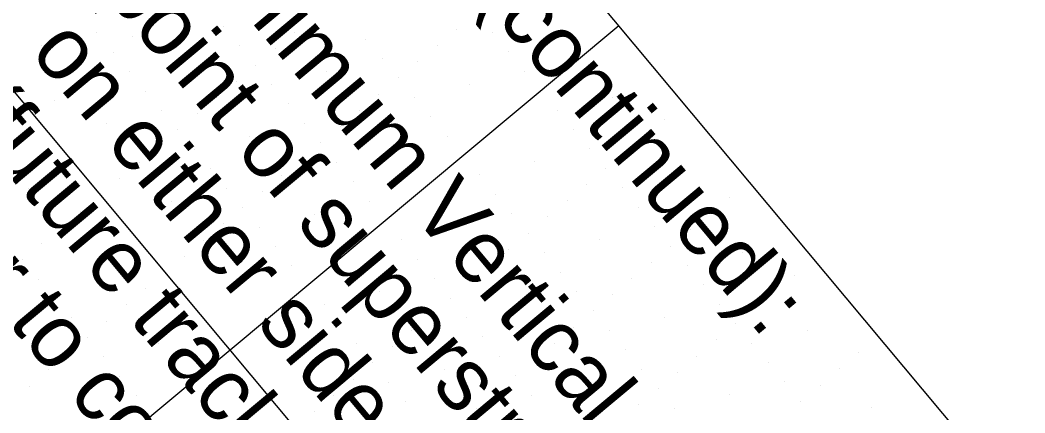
# Model space of a CAD drawing. Extents: x 2042995 to 2043795, y 305365 to 306249.
# Drawn here: x 2043491.39 to 2043531.08, y 305664.77 to 305680.3 of the extents above; entities that cross this region are included whole.
import ezdxf

# ---------------------------------------------------------------- set-up
doc = ezdxf.new("R2010")
doc.units = 0
for name, color, linetype in [('BR_AUTO DIMENSION', 7, 'Continuous'), ('BR_BORDER LINES', 7, 'Continuous'), ('BR_CONCRETE', 7, 'Continuous'), ('BR_GRID DOTS', 7, 'Continuous'), ('BR_GRID LINES', 7, 'Continuous')]:
    doc.layers.add(name, color=color, linetype=linetype)

msp = doc.modelspace()

# ---------------------------------------------------------------- linework, layer by layer
at = {"layer": 'BR_BORDER LINES'}
msp.add_line((2043183.839, 306076.621), (2043615.462, 305559.826), dxfattribs=at)
at = {"layer": 'BR_CONCRETE'}
msp.add_spline([(2043139.109, 306017.548), (2043148.199, 306007.16), (2043160.233, 305993.368), (2043172.245, 305979.557), (2043184.234, 305965.727), (2043196.201, 305951.879), (2043208.145, 305938.012), (2043220.067, 305924.126), (2043231.966, 305910.221), (2043243.843, 305896.297), (2043255.698, 305882.355), (2043267.529, 305868.394), (2043279.339, 305854.414), (2043291.126, 305840.415), (2043302.89, 305826.398), (2043314.632, 305812.361), (2043326.352, 305798.306), (2043338.049, 305784.233), (2043349.724, 305770.14), (2043361.376, 305756.029), (2043373.005, 305741.899), (2043384.613, 305727.75), (2043396.197, 305713.582), (2043407.76, 305699.396), (2043419.299, 305685.191), (2043430.817, 305670.967), (2043442.311, 305656.724), (2043453.784, 305642.463), (2043465.234, 305628.182), (2043476.661, 305613.883), (2043488.066, 305599.566), (2043499.448, 305585.229), (2043510.808, 305570.874), (2043522.146, 305556.5), (2043533.461, 305542.107), (2043544.753, 305527.695), (2043547.219, 305524.543)], degree=3, dxfattribs=at)
at = {"layer": 'BR_GRID DOTS'}
for p, q in [((2043499.415, 305680.053), (2043499.415, 305680.053)), ((2043494.422, 305679.791), (2043494.422, 305679.791)), ((2043495.831, 305679.665), (2043495.831, 305679.665)), ((2043502.232, 305679.8), (2043502.232, 305679.8)), ((2043508.634, 305679.935), (2043508.634, 305679.935)), ((2043510.043, 305679.808), (2043510.043, 305679.808)), ((2043492.246, 305679.277), (2043492.246, 305679.277)), ((2043500.056, 305679.285), (2043500.056, 305679.285)), ((2043501.465, 305679.159), (2043501.465, 305679.159)), ((2043505.049, 305679.547), (2043505.049, 305679.547)), ((2043507.867, 305679.294), (2043507.867, 305679.294)), ((2043495.063, 305679.024), (2043495.063, 305679.024)), ((2043497.88, 305678.771), (2043497.88, 305678.771)), ((2043505.69, 305678.779), (2043505.69, 305678.779)), ((2043510.684, 305679.041), (2043510.684, 305679.041)), ((2043494.296, 305678.383), (2043494.296, 305678.383)), ((2043500.697, 305678.518), (2043500.697, 305678.518)), ((2043507.099, 305678.653), (2043507.099, 305678.653)), ((2043495.704, 305678.256), (2043495.704, 305678.256)), ((2043503.514, 305678.265), (2043503.514, 305678.265)), ((2043506.332, 305678.012), (2043506.332, 305678.012)), ((2043511.325, 305678.273), (2043511.325, 305678.273)), ((2043493.528, 305677.742), (2043493.528, 305677.742)), ((2043499.93, 305677.877), (2043499.93, 305677.877)), ((2043501.338, 305677.75), (2043501.338, 305677.75)), ((2043509.149, 305677.759), (2043509.149, 305677.759)), ((2043496.345, 305677.489), (2043496.345, 305677.489)), ((2043499.162, 305677.236), (2043499.162, 305677.236)), ((2043505.564, 305677.371), (2043505.564, 305677.371)), ((2043506.973, 305677.244), (2043506.973, 305677.244)), ((2043514.783, 305677.253), (2043514.783, 305677.253)), ((2043492.761, 305677.101), (2043492.761, 305677.101)), ((2043501.979, 305676.983), (2043501.979, 305676.983)), ((2043491.993, 305676.46), (2043491.993, 305676.46)), ((2043496.986, 305676.721), (2043496.986, 305676.721)), ((2043498.395, 305676.595), (2043498.395, 305676.595)), ((2043504.796, 305676.73), (2043504.796, 305676.73)), ((2043507.614, 305676.477), (2043507.614, 305676.477)), ((2043512.607, 305676.738), (2043512.607, 305676.738)), ((2043494.81, 305676.207), (2043494.81, 305676.207)), ((2043502.62, 305676.215), (2043502.62, 305676.215)), ((2043504.029, 305676.089), (2043504.029, 305676.089)), ((2043516.832, 305676.359), (2043516.832, 305676.359)), ((2043497.627, 305675.954), (2043497.627, 305675.954)), ((2043500.444, 305675.701), (2043500.444, 305675.701)), ((2043508.255, 305675.709), (2043508.255, 305675.709)), ((2043513.248, 305675.971), (2043513.248, 305675.971)), ((2043516.065, 305675.718), (2043516.065, 305675.718)), ((2043496.86, 305675.313), (2043496.86, 305675.313)), ((2043498.268, 305675.186), (2043498.268, 305675.186)), ((2043503.261, 305675.448), (2043503.261, 305675.448)), ((2043506.079, 305675.195), (2043506.079, 305675.195)), ((2043513.889, 305675.203), (2043513.889, 305675.203)), ((2043502.494, 305674.807), (2043502.494, 305674.807)), ((2043515.297, 305675.077), (2043515.297, 305675.077)), ((2043496.092, 305674.671), (2043496.092, 305674.671)), ((2043498.909, 305674.419), (2043498.909, 305674.419)), ((2043503.902, 305674.68), (2043503.902, 305674.68)), ((2043511.713, 305674.689), (2043511.713, 305674.689)), ((2043514.53, 305674.436), (2043514.53, 305674.436)), ((2043495.325, 305674.03), (2043495.325, 305674.03)), ((2043501.726, 305674.166), (2043501.726, 305674.166)), ((2043509.537, 305674.174), (2043509.537, 305674.174)), ((2043517.347, 305674.183), (2043517.347, 305674.183)), ((2043491.74, 305673.642), (2043491.74, 305673.642)), ((2043499.55, 305673.651), (2043499.55, 305673.651)), ((2043504.543, 305673.913), (2043504.543, 305673.913)), ((2043513.762, 305673.795), (2043513.762, 305673.795)), ((2043515.171, 305673.668), (2043515.171, 305673.668)), ((2043494.557, 305673.389), (2043494.557, 305673.389)), ((2043500.959, 305673.525), (2043500.959, 305673.525)), ((2043510.178, 305673.407), (2043510.178, 305673.407)), ((2043519.396, 305673.289), (2043519.396, 305673.289)), ((2043497.374, 305673.136), (2043497.374, 305673.136)), ((2043500.191, 305672.883), (2043500.191, 305672.883)), ((2043505.185, 305673.145), (2043505.185, 305673.145)), ((2043512.995, 305673.154), (2043512.995, 305673.154)), ((2043515.812, 305672.901), (2043515.812, 305672.901)), ((2043493.79, 305672.748), (2043493.79, 305672.748)), ((2043503.008, 305672.63), (2043503.008, 305672.63)), ((2043510.819, 305672.639), (2043510.819, 305672.639)), ((2043512.227, 305672.513), (2043512.227, 305672.513)), ((2043518.629, 305672.648), (2043518.629, 305672.648)), ((2043493.022, 305672.107), (2043493.022, 305672.107)), ((2043499.424, 305672.242), (2043499.424, 305672.242)), ((2043500.832, 305672.116), (2043500.832, 305672.116)), ((2043508.643, 305672.125), (2043508.643, 305672.125)), ((2043516.453, 305672.133), (2043516.453, 305672.133)), ((2043511.46, 305671.872), (2043511.46, 305671.872)), ((2043514.277, 305671.619), (2043514.277, 305671.619)), ((2043517.861, 305672.007), (2043517.861, 305672.007)), ((2043492.255, 305671.466), (2043492.255, 305671.466)), ((2043498.656, 305671.601), (2043498.656, 305671.601)), ((2043501.473, 305671.348), (2043501.473, 305671.348)), ((2043506.467, 305671.61), (2043506.467, 305671.61)), ((2043510.692, 305671.231), (2043510.692, 305671.231)), ((2043517.094, 305671.366), (2043517.094, 305671.366)), ((2043491.487, 305670.825), (2043491.487, 305670.825)), ((2043497.889, 305670.96), (2043497.889, 305670.96)), ((2043507.108, 305670.842), (2043507.108, 305670.842)), ((2043512.101, 305671.104), (2043512.101, 305671.104)), ((2043519.911, 305671.113), (2043519.911, 305671.113)), ((2043494.304, 305670.572), (2043494.304, 305670.572)), ((2043502.114, 305670.581), (2043502.114, 305670.581)), ((2043509.925, 305670.589), (2043509.925, 305670.589)), ((2043516.326, 305670.725), (2043516.326, 305670.725)), ((2043517.735, 305670.598), (2043517.735, 305670.598)), ((2043492.128, 305670.058), (2043492.128, 305670.058)), ((2043497.121, 305670.319), (2043497.121, 305670.319)), ((2043499.938, 305670.066), (2043499.938, 305670.066)), ((2043507.749, 305670.075), (2043507.749, 305670.075)), ((2043512.742, 305670.336), (2043512.742, 305670.336)), ((2043515.559, 305670.084), (2043515.559, 305670.084)), ((2043521.961, 305670.219), (2043521.961, 305670.219)), ((2043496.354, 305669.678), (2043496.354, 305669.678)), ((2043509.157, 305669.948), (2043509.157, 305669.948)), ((2043518.376, 305669.831), (2043518.376, 305669.831)), ((2043492.769, 305669.29), (2043492.769, 305669.29)), ((2043505.573, 305669.56), (2043505.573, 305669.56)), ((2043508.39, 305669.307), (2043508.39, 305669.307)), ((2043513.383, 305669.569), (2043513.383, 305669.569)), ((2043514.791, 305669.442), (2043514.791, 305669.442)), ((2043521.193, 305669.578), (2043521.193, 305669.578)), ((2043495.586, 305669.037), (2043495.586, 305669.037)), ((2043503.396, 305669.046), (2043503.396, 305669.046)), ((2043511.207, 305669.054), (2043511.207, 305669.054)), ((2043519.017, 305669.063), (2043519.017, 305669.063)), ((2043520.426, 305668.937), (2043520.426, 305668.937)), ((2043493.41, 305668.523), (2043493.41, 305668.523)), ((2043507.622, 305668.666), (2043507.622, 305668.666)), ((2043509.031, 305668.54), (2043509.031, 305668.54)), ((2043514.024, 305668.801), (2043514.024, 305668.801)), ((2043516.841, 305668.548), (2043516.841, 305668.548)), ((2043494.819, 305668.396), (2043494.819, 305668.396)), ((2043504.038, 305668.278), (2043504.038, 305668.278)), ((2043513.256, 305668.16), (2043513.256, 305668.16)), ((2043519.658, 305668.295), (2043519.658, 305668.295)), ((2043522.475, 305668.042), (2043522.475, 305668.042)), ((2043494.051, 305667.755), (2043494.051, 305667.755)), ((2043506.855, 305668.025), (2043506.855, 305668.025)), ((2043509.672, 305667.772), (2043509.672, 305667.772)), ((2043514.665, 305668.034), (2043514.665, 305668.034)), ((2043518.89, 305667.654), (2043518.89, 305667.654)), ((2043496.868, 305667.502), (2043496.868, 305667.502)), ((2043504.679, 305667.511), (2043504.679, 305667.511)), ((2043506.087, 305667.384), (2043506.087, 305667.384)), ((2043512.489, 305667.519), (2043512.489, 305667.519)), ((2043515.306, 305667.266), (2043515.306, 305667.266)), ((2043520.299, 305667.528), (2043520.299, 305667.528)), ((2043493.284, 305667.114), (2043493.284, 305667.114)), ((2043494.692, 305666.988), (2043494.692, 305666.988)), ((2043502.502, 305666.996), (2043502.502, 305666.996)), ((2043510.313, 305667.005), (2043510.313, 305667.005)), ((2043511.721, 305666.878), (2043511.721, 305666.878)), ((2043518.123, 305667.013), (2043518.123, 305667.013)), ((2043524.525, 305667.148), (2043524.525, 305667.148)), ((2043492.516, 305666.473), (2043492.516, 305666.473)), ((2043505.32, 305666.743), (2043505.32, 305666.743)), ((2043508.137, 305666.49), (2043508.137, 305666.49)), ((2043515.947, 305666.499), (2043515.947, 305666.499)), ((2043520.94, 305666.76), (2043520.94, 305666.76)), ((2043523.757, 305666.507), (2043523.757, 305666.507)), ((2043495.333, 305666.22), (2043495.333, 305666.22)), ((2043504.552, 305666.102), (2043504.552, 305666.102)), ((2043510.954, 305666.237), (2043510.954, 305666.237)), ((2043517.355, 305666.372), (2043517.355, 305666.372)), ((2043491.749, 305665.832), (2043491.749, 305665.832)), ((2043505.961, 305665.976), (2043505.961, 305665.976)), ((2043513.771, 305665.984), (2043513.771, 305665.984)), ((2043516.588, 305665.731), (2043516.588, 305665.731)), ((2043521.581, 305665.993), (2043521.581, 305665.993)), ((2043522.99, 305665.866), (2043522.99, 305665.866)), ((2043495.974, 305665.453), (2043495.974, 305665.453)), ((2043503.785, 305665.461), (2043503.785, 305665.461)), ((2043510.186, 305665.596), (2043510.186, 305665.596)), ((2043511.595, 305665.47), (2043511.595, 305665.47)), ((2043519.405, 305665.478), (2043519.405, 305665.478)), ((2043493.798, 305664.938), (2043493.798, 305664.938)), ((2043506.602, 305665.208), (2043506.602, 305665.208)), ((2043509.419, 305664.955), (2043509.419, 305664.955)), ((2043515.82, 305665.09), (2043515.82, 305665.09)), ((2043517.229, 305664.964), (2043517.229, 305664.964)), ((2043522.222, 305665.225), (2043522.222, 305665.225)), ((2043525.039, 305664.972), (2043525.039, 305664.972)), ((2043503.017, 305664.82), (2043503.017, 305664.82))]:
    msp.add_line(p, q, dxfattribs=at)
at = {"layer": 'BR_GRID LINES'}
for p, q in [((2043168.489, 306063.801), (2043600.112, 305547.005)), ((2043515.036, 305680.07), (2043407.583, 305590.326))]:
    msp.add_line(p, q, dxfattribs=at)

# ---------------------------------------------------------------- texts
at = {"layer": 'BR_AUTO DIMENSION'}
for s, p in [('Notes (continued):', (2043503.261, 305688.632)), ('Minimum Vertical Clearance required, measured from top of high rail to lowest', (2043497.504, 305683.824)), ('point of superstructure, in the horizontal clearance area that extends 6\'-0"', (2043494.626, 305681.42)), ('on either side of, and perpendicular to, the centerline of outer tracks', (2043491.748, 305679.016)), ('(future track arrangement). Contractor shall verify top of rail elevations', (2043488.87, 305676.613)), ('prior to construction to confirm minimum clearance requirement is met.', (2043485.992, 305674.209)), ('Future ditches are not shown. See CSX Public Projects Manual for ', (2043480.235, 305669.401)), ('minimum future ditch section. Maintain positive existing ditch drainage.', (2043477.357, 305666.997))]:
    msp.add_text(s, height=2.5, rotation=309.8684, dxfattribs=at).set_placement(p)

doc.saveas('drawing.dxf')
